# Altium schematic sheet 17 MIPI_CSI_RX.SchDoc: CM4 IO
size 420 x 297 mm; Page Create Date: March  8, 1995; Page Number: 17; Page Size: A3; Comment: radxa_1010; Page Count: 19; RevCode: V1.10; Doc: 17 MIPI_CSI_RX; DsnPath: D:\WMS\黄工\[RC126]CM4_IO_V1.10\[RC126]_V1.10\CM4 IO_V1.10.DSN; SchematicName: CM4 IO V1.10; PageName: 17 MIPI_CSI_RX; PageSize: A3; TopSchematic: True
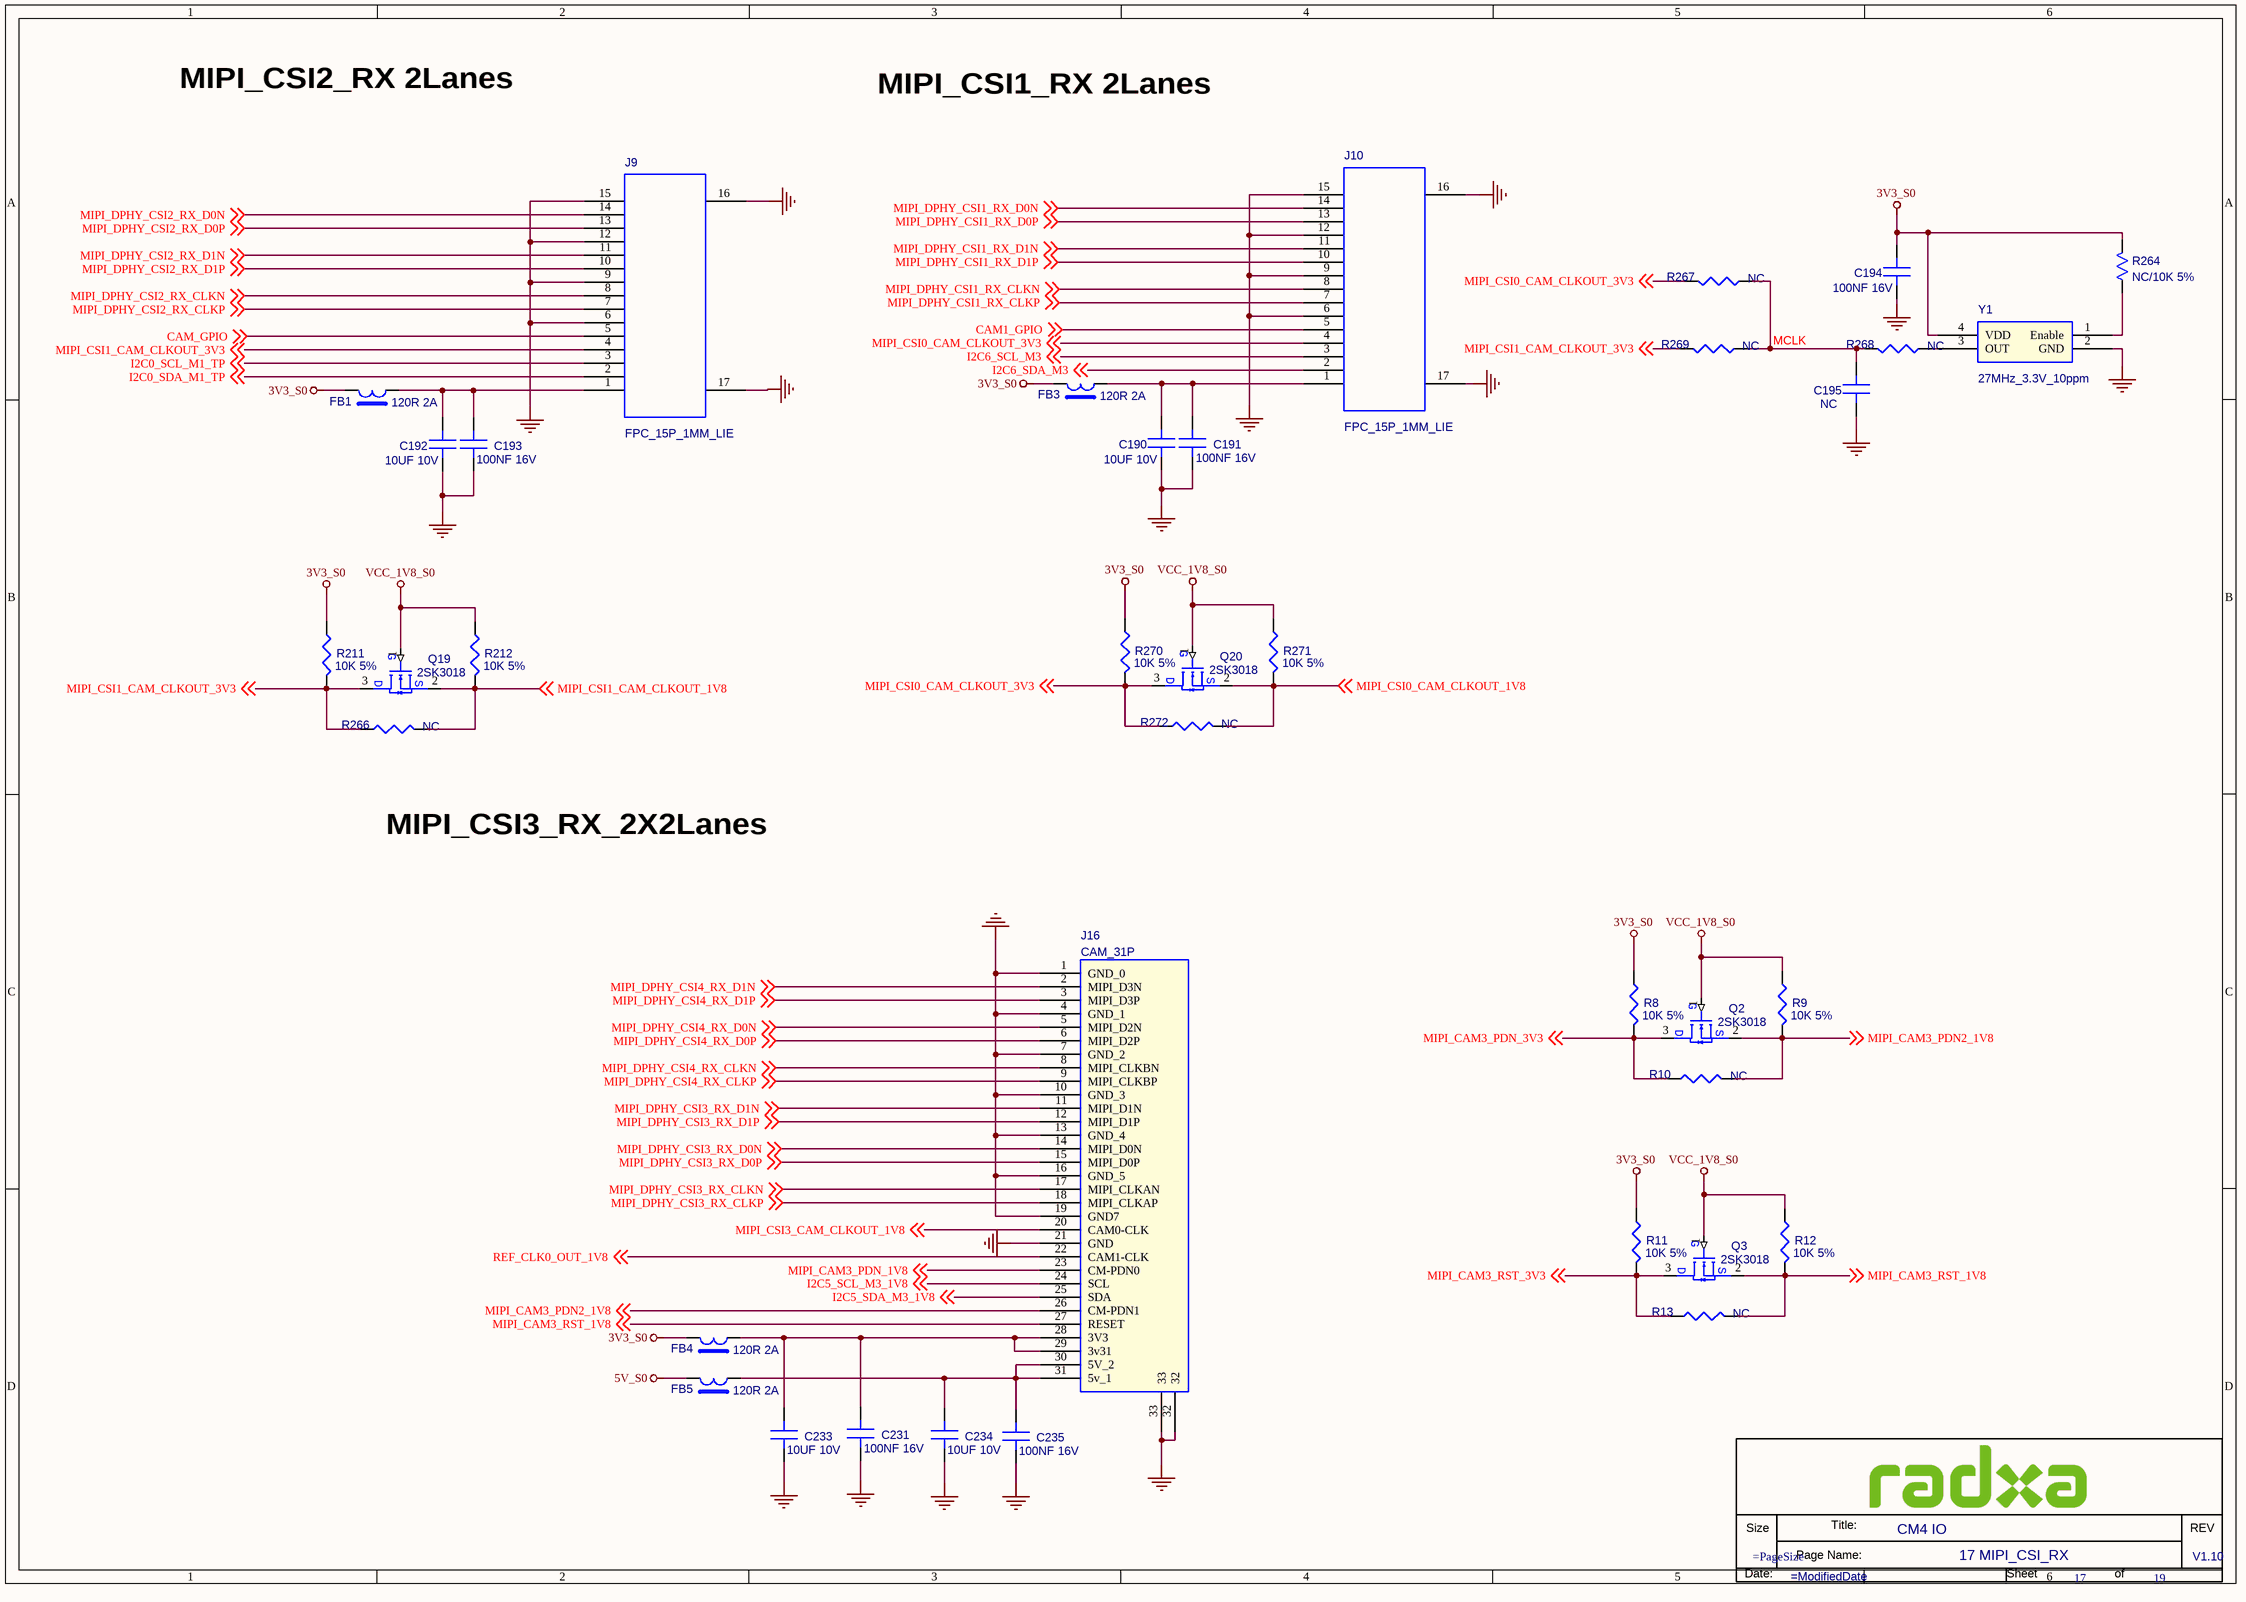
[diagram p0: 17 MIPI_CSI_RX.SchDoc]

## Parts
*  Doc: 17 MIPI_CSI_RX  RevCode: V1.10  Title: CM4 IO  Page Number: 17  Page Count: 19  (hidden comment: radxa_1010)  (graphical)
C190  10UF 10V  [C0402]
C191  100NF 16V  [C0201]
C192  10UF 10V  [C0402]
C193  100NF 16V  [C0201]
C194  100NF 16V  [C0201]
C195  NC  [C0201]
C231  100NF 16V  [C0201]
C233  10UF 10V  [C0402]
C234  10UF 10V  [C0402]
C235  100NF 16V  [C0201]
FB1  120R 2A  [FB0402]
FB3  120R 2A  [FB0402]
FB4  120R 2A  [FB0402]
FB5  120R 2A  [FB0402]
J9  FPC_15P_1MM_LIE  [FPC_15_1D0_LIE]
J10  FPC_15P_1MM_LIE  [FPC_15_1D0_LIE]
J16  CAM_31P  [FPC_31P_0d3_LIE]
Q2  2SK3018  [SOT_323]
Q3  2SK3018  [SOT_323]
Q19  2SK3018  [SOT_323]
Q20  2SK3018  [SOT_323]
R8  10K 5%  [R0402]
R9  10K 5%  [R0402]
R10  NC  [R0402]
R11  10K 5%  [R0402]
R12  10K 5%  [R0402]
R13  NC  [R0402]
R211  10K 5%  [R0402]
R212  10K 5%  [R0402]
R264  NC/10K 5%  [R0201]
R266  NC  [R0402]
R267  NC  [R0402]
R268  NC  [R0402]
R269  NC  [R0402]
R270  10K 5%  [R0402]
R271  10K 5%  [R0402]
R272  NC  [R0402]
Y1  27MHz_3.3V_10ppm  [Y-4-5_08-TXC-7W5]

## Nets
3V3_S0: C194.1 FB1.2 FB3.2 FB4.2 R8.2 R11.2 R211.2 R264.2 R270.2 Y1.4(VDD)
5V_S0: FB5.2
GND: C190.2(B) C191.2(B) C192.2(B) C193.2(B) C194.2 C195.2 C231.2(B) C233.2(B) C234.2(B) C235.2(B) J9.6 J9.9 J9.12 J9.15 J9.16 J9.17 J10.6 J10.9 J10.12 J10.15 J10.16 J10.17 J16.1(GND_0) J16.4(GND_1) J16.7(GND_2) J16.10(GND_3) J16.13(GND_4) J16.16(GND_5) J16.19(GND7) J16.21(GND) J16.32 J16.33 Y1.2(GND)
VCC_1V8_S0: Q2.1(G) Q3.1(G) Q19.1(G) Q20.1(G) R9.2 R12.2 R212.2 R271.2
CAM1_GPIO: J10.5 ; off-sheet CAM1_GPIO
CAM_GPIO: J9.5 ; off-sheet CAM_GPIO
I2C0_SCL_M1_TP: J9.3 ; off-sheet I2C0_SCL_M1_TP
I2C0_SDA_M1_TP: J9.2 ; off-sheet I2C0_SDA_M1_TP
I2C5_SCL_M3_1V8: J16.24(SCL) ; off-sheet I2C5_SCL_M3_1V8
I2C5_SDA_M3_1V8: J16.25(SDA) ; off-sheet I2C5_SDA_M3_1V8
I2C6_SCL_M3: J10.3 ; off-sheet I2C6_SCL_M3
I2C6_SDA_M3: J10.2 ; off-sheet I2C6_SDA_M3
MCLK: C195.1 R267.1 R268.1 R269.1
MIPI_CAM3_PDN2_1V8: J16.26(CM-PDN1) Q2.2(S) R9.1 R10.1 ; off-sheet MIPI_CAM3_PDN2_1V8
MIPI_CAM3_PDN_1V8: J16.23(CM-PDN0) ; off-sheet MIPI_CAM3_PDN_1V8
MIPI_CAM3_PDN_3V3: Q2.3(D) R8.1 R10.2 ; off-sheet MIPI_CAM3_PDN_3V3
MIPI_CAM3_RST_1V8: J16.27(RESET) Q3.2(S) R12.1 R13.1 ; off-sheet MIPI_CAM3_RST_1V8
MIPI_CAM3_RST_3V3: Q3.3(D) R11.1 R13.2 ; off-sheet MIPI_CAM3_RST_3V3
MIPI_CSI0_CAM_CLKOUT_1V8: Q20.2(S) R271.1 R272.1 ; off-sheet MIPI_CSI0_CAM_CLKOUT_1V8
MIPI_CSI0_CAM_CLKOUT_3V3: J10.4 Q20.3(D) R267.2 R270.1 R272.2 ; off-sheet MIPI_CSI0_CAM_CLKOUT_3V3
MIPI_CSI1_CAM_CLKOUT_1V8: Q19.2(S) R212.1 R266.1 ; off-sheet MIPI_CSI1_CAM_CLKOUT_1V8
MIPI_CSI1_CAM_CLKOUT_3V3: J9.4 Q19.3(D) R211.1 R266.2 R269.2 ; off-sheet MIPI_CSI1_CAM_CLKOUT_3V3
MIPI_CSI3_CAM_CLKOUT_1V8: J16.20(CAM0-CLK) ; off-sheet MIPI_CSI3_CAM_CLKOUT_1V8
MIPI_DPHY_CSI1_RX_CLKN: J10.8 ; off-sheet MIPI_DPHY_CSI1_RX_CLKN
MIPI_DPHY_CSI1_RX_CLKP: J10.7 ; off-sheet MIPI_DPHY_CSI1_RX_CLKP
MIPI_DPHY_CSI1_RX_D0N: J10.14 ; off-sheet MIPI_DPHY_CSI1_RX_D0N
MIPI_DPHY_CSI1_RX_D0P: J10.13 ; off-sheet MIPI_DPHY_CSI1_RX_D0P
MIPI_DPHY_CSI1_RX_D1N: J10.11 ; off-sheet MIPI_DPHY_CSI1_RX_D1N
MIPI_DPHY_CSI1_RX_D1P: J10.10 ; off-sheet MIPI_DPHY_CSI1_RX_D1P
MIPI_DPHY_CSI2_RX_CLKN: J9.8 ; off-sheet MIPI_DPHY_CSI2_RX_CLKN
MIPI_DPHY_CSI2_RX_CLKP: J9.7 ; off-sheet MIPI_DPHY_CSI2_RX_CLKP
MIPI_DPHY_CSI2_RX_D0N: J9.14 ; off-sheet MIPI_DPHY_CSI2_RX_D0N
MIPI_DPHY_CSI2_RX_D0P: J9.13 ; off-sheet MIPI_DPHY_CSI2_RX_D0P
MIPI_DPHY_CSI2_RX_D1N: J9.11 ; off-sheet MIPI_DPHY_CSI2_RX_D1N
MIPI_DPHY_CSI2_RX_D1P: J9.10 ; off-sheet MIPI_DPHY_CSI2_RX_D1P
MIPI_DPHY_CSI3_RX_CLKN: J16.17(MIPI_CLKAN) ; off-sheet MIPI_DPHY_CSI3_RX_CLKN
MIPI_DPHY_CSI3_RX_CLKP: J16.18(MIPI_CLKAP) ; off-sheet MIPI_DPHY_CSI3_RX_CLKP
MIPI_DPHY_CSI3_RX_D0N: J16.14(MIPI_D0N) ; off-sheet MIPI_DPHY_CSI3_RX_D0N
MIPI_DPHY_CSI3_RX_D0P: J16.15(MIPI_D0P) ; off-sheet MIPI_DPHY_CSI3_RX_D0P
MIPI_DPHY_CSI3_RX_D1N: J16.11(MIPI_D1N) ; off-sheet MIPI_DPHY_CSI3_RX_D1N
MIPI_DPHY_CSI3_RX_D1P: J16.12(MIPI_D1P) ; off-sheet MIPI_DPHY_CSI3_RX_D1P
MIPI_DPHY_CSI4_RX_CLKN: J16.8(MIPI_CLKBN) ; off-sheet MIPI_DPHY_CSI4_RX_CLKN
MIPI_DPHY_CSI4_RX_CLKP: J16.9(MIPI_CLKBP) ; off-sheet MIPI_DPHY_CSI4_RX_CLKP
MIPI_DPHY_CSI4_RX_D0N: J16.5(MIPI_D2N) ; off-sheet MIPI_DPHY_CSI4_RX_D0N
MIPI_DPHY_CSI4_RX_D0P: J16.6(MIPI_D2P) ; off-sheet MIPI_DPHY_CSI4_RX_D0P
MIPI_DPHY_CSI4_RX_D1N: J16.2(MIPI_D3N) ; off-sheet MIPI_DPHY_CSI4_RX_D1N
MIPI_DPHY_CSI4_RX_D1P: J16.3(MIPI_D3P) ; off-sheet MIPI_DPHY_CSI4_RX_D1P
REF_CLK0_OUT_1V8: J16.22(CAM1-CLK) ; off-sheet REF_CLK0_OUT_1V8
NetC190_1: C190.1(A) C191.1(A) FB3.1 J10.1
NetC192_1: C192.1(A) C193.1(A) FB1.1 J9.1
NetC231_1: C231.1(A) C233.1(A) FB4.1 J16.28(3V3) J16.29(3v31)
NetC234_1: C234.1(A) C235.1(A) FB5.1 J16.30(5V_2) J16.31(5v_1)
NetR264_1: R264.1 Y1.1(Enable)
NetR268_2: R268.2 Y1.3(OUT)

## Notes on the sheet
- MIPI_CSI2_RX 2Lanes
- MIPI_CSI1_RX 2Lanes
- MIPI_CSI3_RX_2X2Lanes

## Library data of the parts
C190 = C: SMD  0402  10UF  10V  X5R  ±20%  ROHS; PARTS: 1; Part Reference: C190; Part Number: A1C01.00025; OriginalSymbolOrigin: (0,30); PKG_TYPE: CAP2-100-250; LEVEL: STD; PINSWAP: (A,B); Preferred: 6715f349cd0bc5
C191 = C: SMD  0201  100NF  16V  X5R  ±20%  ROHS; PARTS: 1; Part Reference: C191; Part Number: A1C01.00099; OriginalSymbolOrigin: (0,30); PKG_TYPE: CAP2-100-250; LEVEL: STD; PINSWAP: (A,B); Preferred: 6715f349cd0bc5
C192 = C: SMD  0402  10UF  10V  X5R  ±20%  ROHS; PARTS: 1; Part Reference: C192; Part Number: A1C01.00025; OriginalSymbolOrigin: (0,30); PKG_TYPE: CAP2-100-250; LEVEL: STD; PINSWAP: (A,B); Preferred: 6715f349cd0bc5
C193 = C: SMD  0201  100NF  16V  X5R  ±20%  ROHS; PARTS: 1; Part Reference: C193; Part Number: A1C01.00099; OriginalSymbolOrigin: (0,30); PKG_TYPE: CAP2-100-250; LEVEL: STD; PINSWAP: (A,B); Preferred: 6715f349cd0bc5
C194 = C_Dup1: SMD  0201  100NF  16V  X5R  ±20%  ROHS; PARTS: 1; Part Reference: C194; Part Number: A1C01.00099; OriginalSymbolOrigin: (0,30); PKG_TYPE: CAP2-100-250; LEVEL: STD; PINSWAP: (A,B); Preferred: 6715f349cd0bc5; ROOM: DVDD_MEDIA; Grade: B; Approved: 已承认
C195 = C_Dup1: SMD  0201  10PF  50V  NPO  ±5%  ROHS; PARTS: 1; Part Reference: C195; Part Number: A1C01.00141; OriginalSymbolOrigin: (0,30); PKG_TYPE: CAP2-100-250; LEVEL: STD; PINSWAP: (A,B); Preferred: 6715f349cd0bc5; Approved: 已承认; Grade: B; ROOM: AN41908
C231 = C: SMD  0201  100NF  16V  X5R  ±20%  ROHS; PARTS: 1; Part Reference: C231; Part Number: A1C01.00099; OriginalSymbolOrigin: (0,30); PKG_TYPE: CAP2-100-250; LEVEL: STD; PINSWAP: (A,B); Preferred: 6715f349cd0bc5
C233 = C: SMD  0402  10UF  10V  X5R  ±20%  ROHS; PARTS: 1; Part Reference: C233; Part Number: A1C01.00025; OriginalSymbolOrigin: (0,30); PKG_TYPE: CAP2-100-250; LEVEL: STD; PINSWAP: (A,B); Preferred: 6715f349cd0bc5
C234 = C: SMD  0402  10UF  10V  X5R  ±20%  ROHS; PARTS: 1; Part Reference: C234; Part Number: A1C01.00025; OriginalSymbolOrigin: (0,30); PKG_TYPE: CAP2-100-250; LEVEL: STD; PINSWAP: (A,B); Preferred: 6715f349cd0bc5
C235 = C: SMD  0201  100NF  16V  X5R  ±20%  ROHS; PARTS: 1; Part Reference: C235; Part Number: A1C01.00099; OriginalSymbolOrigin: (0,30); PKG_TYPE: CAP2-100-250; LEVEL: STD; PINSWAP: (A,B); Preferred: 6715f349cd0bc5
FB1 = BEAD: SMD  0402  FB120R  2A  ±25%  ROHS; Part Reference: FB1; Part Number: A1L09.00004; Preferred: 6715f349cd0bc5; Temp Coeff: -55℃ to +125℃
FB3 = BEAD: SMD  0402  FB120R  2A  ±25%  ROHS; Part Reference: FB3; Part Number: A1L09.00004; Preferred: 6715f349cd0bc5; Temp Coeff: -55℃ to +125℃
FB4 = BEAD: SMD  0402  FB120R  2A  ±25%  ROHS; Part Reference: FB4; Part Number: A1L09.00004; Temp Coeff: -55℃ to +125℃; Preferred: 6715f349cd0bc5
FB5 = BEAD: SMD  0402  FB120R  2A  ±25%  ROHS; Part Reference: FB5; Part Number: A1L09.00004; Preferred: 6715f349cd0bc5; Temp Coeff: -55℃ to +125℃
J9 = FPC_15P_LIE: SMD  翻盖式下接触  卧式  15PIN  180度  1.0mm脚距  H2.0  FPC-1.0FX-15PWCR-H20  XUNPU(讯普)  ROHS; Part Reference: J9; Part Number: A1J06.00025; OriginalSymbolOrigin: (-150,450); Preferred: 6715f349cd0bc5; Temp Coeff: -40℃ to +85℃
J10 = FPC_15P_LIE: SMD  翻盖式下接触  卧式  15PIN  180度  1.0mm脚距  H2.0  FPC-1.0FX-15PWCR-H20  XUNPU(讯普)  ROHS; Part Reference: J10; Part Number: A1J06.00025; OriginalSymbolOrigin: (-150,450); Temp Coeff: -40℃ to +85℃; Preferred: 6715f349cd0bc5
J16 = CAM_31P: SMD  上下接触  卧式  31PIN  0.3mm脚距  后翻盖H1.0  FH35C-31S-0.3SHW(50)  镀金  广濑  ROHS; Part Reference: J16; Part Number: A1J06.00002
Q2 = MOSFET_NPN: SMD  编带  SOT-323  2SK3018  N沟道  长晶  ROHS; Part Reference: Q2; Part Number: A1D01.00007; Temp Coeff: -55℃ to ＋150℃
Q3 = MOSFET_NPN: SMD  编带  SOT-323  2SK3018  N沟道  长晶  ROHS; Part Reference: Q3; Part Number: A1D01.00007; Temp Coeff: -55℃ to ＋150℃
Q19 = MOSFET_NPN: SMD  编带  SOT-323  2SK3018  N沟道  长晶  ROHS; Part Reference: Q19; Part Number: A1D01.00007; Temp Coeff: -55℃ to ＋150℃
Q20 = MOSFET_NPN: SMD  编带  SOT-323  2SK3018  N沟道  长晶  ROHS; Part Reference: Q20; Part Number: A1D01.00007; Temp Coeff: -55℃ to ＋150℃
R8 = R: SMD  0201  10K  1/20W  ±5%  ROHS; Part Reference: R8; Part Number: A1R01.00012; PCB Footprint: R0201; Preferred: 6715f349cd0bc5; Temp Coeff: -55℃ to +125℃
R9 = R: SMD  0201  10K  1/20W  ±5%  ROHS; Part Reference: R9; Part Number: A1R01.00012; PCB Footprint: R0201; Preferred: 6715f349cd0bc5; Temp Coeff: -55℃ to +125℃
R10 = R: SMD  0201  0R  1/20W  ±5%  ROHS; Part Reference: R10; Part Number: A1R01.00027; PCB Footprint: R0201; Temp Coeff: -55℃ to +125℃; Preferred: 6715f349cd0bc5
R11 = R: SMD  0201  10K  1/20W  ±5%  ROHS; Part Reference: R11; Part Number: A1R01.00012; PCB Footprint: R0201; Preferred: 6715f349cd0bc5; Temp Coeff: -55℃ to +125℃
R12 = R: SMD  0201  10K  1/20W  ±5%  ROHS; Part Reference: R12; Part Number: A1R01.00012; PCB Footprint: R0201; Preferred: 6715f349cd0bc5; Temp Coeff: -55℃ to +125℃
R13 = R: SMD  0201  0R  1/20W  ±5%  ROHS; Part Reference: R13; Part Number: A1R01.00027; PCB Footprint: R0201; Temp Coeff: -55℃ to +125℃; Preferred: 6715f349cd0bc5
R211 = R: SMD  0201  10K  1/20W  ±5%  ROHS; Part Reference: R211; Part Number: A1R01.00012; PCB Footprint: R0201; Preferred: 6715f349cd0bc5; Temp Coeff: -55℃ to +125℃
R212 = R: SMD  0201  10K  1/20W  ±5%  ROHS; Part Reference: R212; Part Number: A1R01.00012; PCB Footprint: R0201; Preferred: 6715f349cd0bc5; Temp Coeff: -55℃ to +125℃
R264 = R_Dup1: SMD  0201  10K  1/20W  ±5%  ROHS; PARTS: 1; Part Reference: R264; Part Number: A1R01.00012; LEVEL: STD; PKG_TYPE: 2; PINSWAP: (A,B); OriginalSymbolOrigin: (10,20); ROOM: DC-IRIS; Grade: B; Approved: 已承认; Temp Coeff: -55℃ to +125℃; Preferred: 6715f349cd0bc5
R266 = R: SMD  0201  0R  1/20W  ±5%  ROHS; Part Reference: R266; Part Number: A1R01.00027; PCB Footprint: R0201; Temp Coeff: -55℃ to +125℃; Preferred: 6715f349cd0bc5
R267 = R: SMD  0201  0R  1/20W  ±5%  ROHS; Part Reference: R267; Part Number: A1R01.00027; PCB Footprint: R0201; Temp Coeff: -55℃ to +125℃; Preferred: 6715f349cd0bc5
R268 = R: SMD  0201  0R  1/20W  ±5%  ROHS; Part Reference: R268; Part Number: A1R01.00027; PCB Footprint: R0201; Preferred: 6715f349cd0bc5; Temp Coeff: -55℃ to +125℃
R269 = R: SMD  0201  0R  1/20W  ±5%  ROHS; Part Reference: R269; Part Number: A1R01.00027; PCB Footprint: R0201; Preferred: 6715f349cd0bc5; Temp Coeff: -55℃ to +125℃
R270 = R: SMD  0201  10K  1/20W  ±5%  ROHS; Part Reference: R270; Part Number: A1R01.00012; PCB Footprint: R0201; Preferred: 6715f349cd0bc5; Temp Coeff: -55℃ to +125℃
R271 = R: SMD  0201  10K  1/20W  ±5%  ROHS; Part Reference: R271; Part Number: A1R01.00012; PCB Footprint: R0201; Preferred: 6715f349cd0bc5; Temp Coeff: -55℃ to +125℃
R272 = R: SMD  0201  0R  1/20W  ±5%  ROHS; Part Reference: R272; Part Number: A1R01.00027; PCB Footprint: R0201; Temp Coeff: -55℃ to +125℃; Preferred: 6715f349cd0bc5
Y1 = OSC_4P_V: SMD  有源  3225  27MHz  3.3V  ±10ppm  晶灏  3N27.000E33YCG  ROHS; Part Reference: Y1; Part Number: A1Y01.00074; Preferred: 6715f349cd0bc5; Temp Coeff: -40℃ to +85℃; PCB Footprint: OSC_SM4_3D2X2D5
